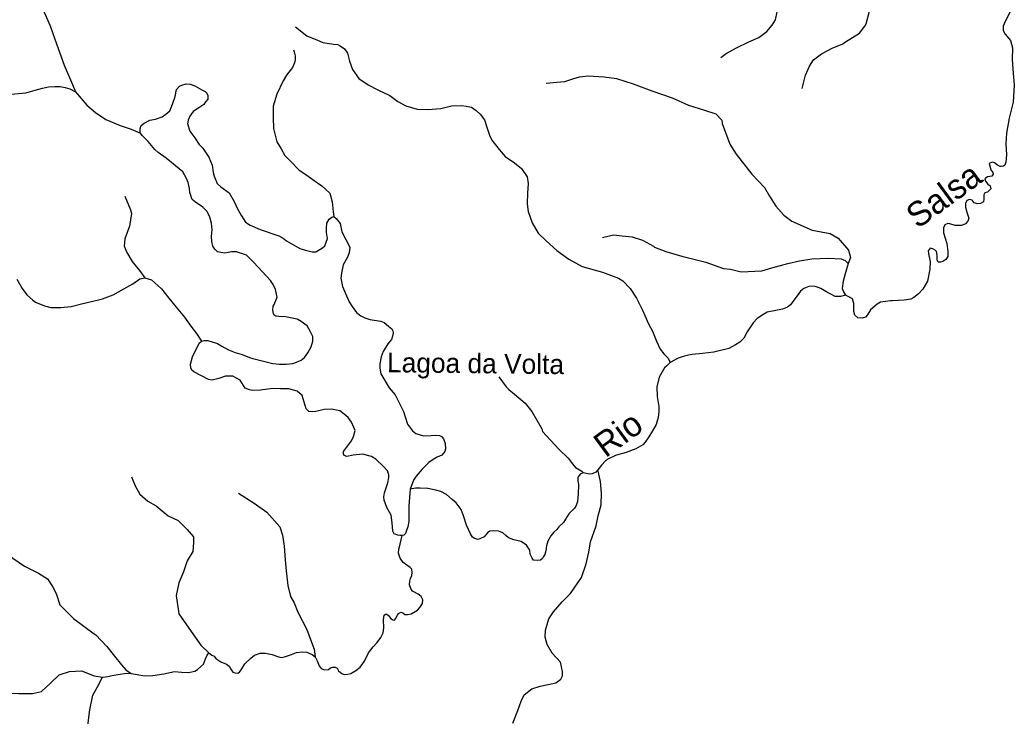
# Model space of a CAD drawing. Extents: x 436.3 to 500.4, y 8231 to 8286.4.
# Drawn here: x 484.1 to 492.19, y 8252.95 to 8258.62 of the extents above; entities that cross this region are included whole.
import ezdxf
from ezdxf.enums import TextEntityAlignment as Align

# ---------------------------------------------------------------- set-up
doc = ezdxf.new("R2010")
doc.units = 0
doc.header["$LTSCALE"] = 0.08
doc.linetypes.add('LONG_DASHED', pattern=[7.5, 6, -1.5])
doc.layers.add('2', color=7, linetype='Continuous', lineweight=25)
doc.layers.add('9', color=7, linetype='LONG_DASHED', lineweight=25)
doc.layers.add('61', color=7, linetype='Continuous')

msp = doc.modelspace()

# ---------------------------------------------------------------- linework, layer by layer
at = {"layer": '2'}
for points in [[(485.0847, 8257.6929), (485.0821, 8257.7061), (485.082, 8257.7324), (485.0899, 8257.7561), (485.1137, 8257.7746), (485.1602, 8257.8), (485.2053, 8257.809), (485.2594, 8257.8271), (485.2909, 8257.8495), (485.3225, 8257.8765), (485.3449, 8257.9304), (485.3673, 8257.9932), (485.3781, 8258.0488), (485.4019, 8258.0752), (485.4204, 8258.0858), (485.4549, 8258.0963), (485.4894, 8258.0937), (485.5265, 8258.0779), (485.5822, 8258.0464), (485.6114, 8258.0333), (485.6247, 8258.0201), (485.6328, 8258.0017), (485.6328, 8257.9701), (485.6142, 8257.9491), (485.5984, 8257.928), (485.5587, 8257.8989), (485.5138, 8257.87), (485.485, 8257.8319), (485.4715, 8257.8004), (485.4671, 8257.769), (485.4853, 8257.7107), (485.526, 8257.6569), (485.5622, 8257.6031), (485.5917, 8257.5731), (485.6391, 8257.5), (485.6663, 8257.4328), (485.6755, 8257.3744), (485.6846, 8257.343), (485.7072, 8257.2847), (485.7389, 8257.2578), (485.8066, 8257.2085), (485.8474, 8257.1368), (485.8746, 8257.0785), (485.9063, 8257.0201), (485.9379, 8256.9708), (485.9774, 8256.9466), (486.057, 8256.9098), (486.2088, 8256.8589), (486.245, 8256.841), (486.2721, 8256.8186), (486.3804, 8256.7558), (486.4256, 8256.7424), (486.4797, 8256.729), (486.5113, 8256.729), (486.5654, 8256.7605), (486.5834, 8256.7785), (486.6059, 8256.8369), (486.5968, 8256.8863), (486.5967, 8256.9222), (486.6011, 8256.9626), (486.6189, 8256.9948), (486.64, 8257.0107), (486.656, 8257.0159)], [(485.7714, 8256.719), (485.737, 8256.7218), (485.7104, 8256.7296), (485.6892, 8256.7507), (485.6732, 8256.7744), (485.6653, 8256.8113), (485.6629, 8256.8536), (485.6673, 8256.9075), (485.6627, 8256.9614), (485.6491, 8257.0108), (485.6265, 8257.0557), (485.5903, 8257.0915), (485.5316, 8257.1318), (485.5045, 8257.1542), (485.4863, 8257.2126), (485.4817, 8257.244), (485.4726, 8257.2934), (485.459, 8257.3248), (485.4273, 8257.3786), (485.2917, 8257.4906), (485.2285, 8257.5354), (485.2014, 8257.5623), (485.1471, 8257.625), (485.0974, 8257.6743), (485.0847, 8257.6929)], [(486.656, 8257.0159), (486.6772, 8257.0001), (486.7091, 8256.958), (486.7231, 8256.8909), (486.7864, 8256.7653), (486.782, 8256.7204), (486.7685, 8256.6844), (486.7325, 8256.6215), (486.7191, 8256.5541)], [(486.1643, 8256.4635), (486.1417, 8256.4949), (486.0061, 8256.643), (485.9464, 8256.7009), (485.8661, 8256.7282), (485.8255, 8256.7281), (485.7714, 8256.719)], [(486.7191, 8256.5541), (486.7146, 8256.5137), (486.7282, 8256.4463), (486.7599, 8256.3699), (486.7825, 8256.3205), (486.8051, 8256.2845), (486.8412, 8256.2351)], [(485.5801, 8256.0018), (485.6013, 8256.0071), (485.6332, 8256.0072), (485.71, 8255.9835), (485.7472, 8255.9599), (485.7991, 8255.9323), (485.8533, 8255.9099), (485.9119, 8255.892), (485.9706, 8255.8696), (485.9977, 8255.8606), (486.1601, 8255.8204), (486.2142, 8255.816), (486.2684, 8255.816), (486.3225, 8255.8206), (486.3541, 8255.8296), (486.3902, 8255.8477), (486.4173, 8255.8702), (486.4443, 8255.9063), (486.4714, 8255.9558), (486.4868, 8256.0031), (486.4868, 8256.0401), (486.4683, 8256.0771), (486.4398, 8256.1267), (486.3901, 8256.1626), (486.3585, 8256.1806), (486.3179, 8256.1895), (486.2637, 8256.1984), (486.2096, 8256.2028), (486.1845, 8256.206), (486.1712, 8256.2139), (486.166, 8256.227), (486.1606, 8256.2534), (486.1632, 8256.2878), (486.1711, 8256.301), (486.1959, 8256.3602), (486.1823, 8256.4231), (486.1643, 8256.4635)], [(486.8412, 8256.2351), (486.8773, 8256.2082), (486.9089, 8256.1903), (486.9495, 8256.1768), (487.0387, 8256.1647), (487.0653, 8256.1541), (487.1024, 8256.1225), (487.1303, 8256.1014), (487.1382, 8256.0856), (487.1408, 8256.0698), (487.1356, 8256.0434), (487.125, 8256.0143), (487.0958, 8255.98), (487.0588, 8255.9165), (487.0428, 8255.8742), (487.0308, 8255.817), (487.0308, 8255.781), (487.0398, 8255.736), (487.1074, 8255.6234), (487.1569, 8255.5649), (487.2244, 8255.4298), (487.2558, 8255.3262), (487.2963, 8255.2721), (487.3233, 8255.2496), (487.3864, 8255.2316), (487.4488, 8255.2334), (487.4806, 8255.236), (487.5176, 8255.2334), (487.5335, 8255.2255), (487.5493, 8255.207), (487.5625, 8255.1699), (487.5651, 8255.1223), (487.5598, 8255.1037), (487.5359, 8255.0746), (487.4988, 8255.0587), (487.4644, 8255.0402), (487.4311, 8255.0151), (487.3769, 8254.9609), (487.3272, 8254.9023), (487.3046, 8254.8707), (487.2775, 8254.7985)], [(487.2123, 8254.4221), (487.1938, 8254.4221), (487.1779, 8254.4247), (487.1489, 8254.4354), (487.1383, 8254.4565), (487.1327, 8254.5231), (487.1238, 8254.5863), (487.0879, 8254.6495), (487.0655, 8254.7081), (487.0628, 8254.7355), (487.0682, 8254.7673), (487.0975, 8254.8493), (487.1055, 8254.8917), (487.1055, 8254.9156), (487.0924, 8254.9473), (487.0633, 8254.979), (486.9985, 8255.0419), (486.9624, 8255.0645), (486.8903, 8255.0824), (486.8137, 8255.0734), (486.764, 8255.0636), (486.7402, 8255.0715), (486.7349, 8255.0847), (486.7349, 8255.1033), (486.8003, 8255.1906), (486.8184, 8255.2267), (486.832, 8255.2763), (486.8005, 8255.3438), (486.7734, 8255.3798), (486.7419, 8255.4069), (486.7058, 8255.4338), (486.6382, 8255.4473), (486.5795, 8255.4472), (486.5119, 8255.4291), (486.4809, 8255.4257), (486.4543, 8255.4309), (486.4332, 8255.452), (486.3992, 8255.5596), (486.3586, 8255.5956), (486.2909, 8255.6135), (486.2232, 8255.6134), (486.1601, 8255.6178), (486.0608, 8255.6042), (485.9976, 8255.5996), (485.9698, 8255.6048), (485.9354, 8255.6207), (485.8939, 8255.685), (485.8352, 8255.7164), (485.7766, 8255.7163), (485.7224, 8255.6982), (485.6683, 8255.6846), (485.6367, 8255.6891), (485.5194, 8255.7519), (485.5006, 8255.7667), (485.4926, 8255.7851), (485.49, 8255.8142), (485.5086, 8255.8749), (485.5616, 8255.986), (485.5801, 8256.0018)], [(487.2775, 8254.7985), (487.2682, 8254.6631), (487.2679, 8254.5366), (487.2601, 8254.491), (487.2494, 8254.4619), (487.2389, 8254.438), (487.2255, 8254.4248), (487.2123, 8254.4221)]]:
    msp.add_lwpolyline(points, dxfattribs=at)
at = {"layer": '9'}
for points in [[(481.9907, 8259.6476), (482.0749, 8259.5359), (482.1958, 8259.4436), (482.3057, 8259.4173), (482.4206, 8259.4226), (482.576, 8259.4332), (482.728, 8259.4578), (482.8587, 8259.4684), (482.9719, 8259.4473), (483.1771, 8259.405), (483.354, 8259.3628), (483.6512, 8259.3031), (483.7893, 8259.2609), (483.8886, 8259.2118), (484.0056, 8259.1308), (484.1034, 8259.0383), (484.1461, 8258.9784), (484.2137, 8258.8624), (484.2635, 8258.7639), (484.349, 8258.5669), (484.3882, 8258.4578), (484.4632, 8258.2467), (484.531, 8258.0902), (484.5562, 8258.0303)], [(489.8053, 8258.3089), (489.8484, 8258.3426), (489.9336, 8258.3874), (490.0338, 8258.4371), (490.114, 8258.4719), (490.1791, 8258.5217), (490.2241, 8258.5716), (490.2492, 8258.6165), (490.2641, 8258.6815), (490.3192, 8258.7514), (490.3592, 8258.7813), (490.4344, 8258.8261), (490.5145, 8258.8409), (490.6048, 8258.8407), (490.6901, 8258.8355), (490.8857, 8258.8051), (490.9758, 8258.8084), (491.0602, 8258.822)], [(490.4661, 8258.0568), (490.4932, 8258.1656), (490.5281, 8258.2394), (490.5592, 8258.2899), (490.6253, 8258.3402), (490.711, 8258.3867), (490.7968, 8258.4215), (490.8201, 8258.437), (490.9331, 8258.5067), (490.9759, 8258.5649), (490.9876, 8258.5844), (491.0114, 8258.6752), (491.0238, 8258.743), (491.0602, 8258.822)], [(492.1629, 8258.686), (492.1194, 8258.6031), (492.1036, 8258.5637), (492.1037, 8258.5282), (492.1196, 8258.5006), (492.1633, 8258.447), (492.1792, 8258.3878), (492.1755, 8258.2931), (492.1836, 8258.1827), (492.1916, 8258.0841), (492.184, 8257.946), (492.1525, 8257.8158), (492.1289, 8257.6934), (492.1249, 8257.6079), (492.1283, 8257.517), (492.1245, 8257.4578), (492.1166, 8257.4341), (492.1047, 8257.4263), (492.0849, 8257.4223), (492.077, 8257.4223), (492.0571, 8257.4341), (492.0333, 8257.4538), (492.0135, 8257.4578), (491.9897, 8257.446), (492.0017, 8257.3947), (492.0175, 8257.3749), (492.0215, 8257.3591), (492.0097, 8257.3433), (491.974, 8257.3394), (491.9542, 8257.3235), (491.9582, 8257.3038), (491.9781, 8257.2801), (491.9979, 8257.2644), (492.0019, 8257.2406), (491.9742, 8257.213), (491.9544, 8257.209), (491.9464, 8257.1932), (491.9464, 8257.1577), (491.9426, 8257.134), (491.9188, 8257.1222), (491.891, 8257.1182), (491.8673, 8257.1262), (491.8514, 8257.1499), (491.8276, 8257.1538), (491.8078, 8257.1459), (491.7959, 8257.1222), (491.796, 8257.0906), (491.8079, 8257.0511), (491.8225, 8257.0028), (491.8146, 8256.979), (491.7948, 8256.9553), (491.7631, 8256.9435), (491.7116, 8256.9435), (491.668, 8256.9554), (491.6521, 8256.9594), (491.6284, 8256.9475), (491.6165, 8256.9238), (491.6165, 8256.8843), (491.6444, 8256.7973), (491.6523, 8256.7301), (491.6524, 8256.6906), (491.6366, 8256.6669), (491.6129, 8256.6511), (491.593, 8256.6432), (491.5732, 8256.6432), (491.5652, 8256.663), (491.5652, 8256.7026), (491.5613, 8256.7302), (491.5494, 8256.7421), (491.5295, 8256.7539), (491.5094, 8256.7576), (491.4936, 8256.7378), (491.4976, 8256.6982), (491.5095, 8256.6508), (491.5056, 8256.5876), (491.4859, 8256.4887), (491.4503, 8256.4255), (491.4146, 8256.386), (491.375, 8256.3583), (491.3513, 8256.3425)], [(486.3461, 8258.5589), (486.4368, 8258.4864), (486.5244, 8258.4517), (486.5683, 8258.4315), (486.6534, 8258.4193), (486.6884, 8258.4164), (486.7088, 8258.4048), (486.7439, 8258.3788), (486.7674, 8258.344), (486.785, 8258.2802), (486.8085, 8258.2107), (486.8612, 8258.1383), (486.9372, 8258.0861), (487.016, 8258.0456), (487.1125, 8257.9992), (487.1767, 8257.9528), (487.2439, 8257.9151), (487.3343, 8257.8891), (487.4218, 8257.8862), (487.5278, 8257.8941), (487.6152, 8257.9173), (487.6938, 8257.9201), (487.7347, 8257.9143), (487.7784, 8257.9056), (487.8164, 8257.8795), (487.8485, 8257.8476), (487.8836, 8257.8012), (487.9012, 8257.7433), (487.9246, 8257.6766), (487.9422, 8257.6359), (488.0012, 8257.5622), (488.051, 8257.5042), (488.1268, 8257.4519), (488.1851, 8257.4055), (488.2289, 8257.3388), (488.2377, 8257.2837), (488.2321, 8257.2053), (488.2295, 8257.1184), (488.2383, 8257.0575), (488.2706, 8256.9647), (488.3203, 8256.8792), (488.3844, 8256.8182), (488.4718, 8256.7398), (488.5679, 8256.67), (488.6785, 8256.6088), (488.8442, 8256.562), (488.9721, 8256.5153), (489.007, 8256.4919), (489.0688, 8256.4292), (489.1182, 8256.3506), (489.1677, 8256.2546), (489.2171, 8256.1441), (489.2491, 8256.083), (489.2811, 8256.0015), (489.3131, 8255.9374), (489.3421, 8255.8996), (489.3769, 8255.8646), (489.3925, 8255.8288)], [(486.3287, 8258.3725), (486.3345, 8258.3551), (486.3434, 8258.3232), (486.3435, 8258.2913), (486.3376, 8258.2653), (486.3203, 8258.2275), (486.2707, 8258.1667), (486.2445, 8258.1202), (486.1923, 8258.01), (486.1633, 8257.9142), (486.1635, 8257.8215), (486.1666, 8257.7316), (486.1932, 8257.6243), (486.2284, 8257.5663), (486.2578, 8257.5125), (486.3075, 8257.4632), (486.3748, 8257.3937), (486.4362, 8257.3531), (486.4976, 8257.3097), (486.559, 8257.2662), (486.6233, 8257.2054), (486.6439, 8257.1358), (486.6529, 8257.0545), (486.656, 8257.0159)], [(488.3834, 8258.1009), (488.4703, 8258.1094), (488.5355, 8258.1136), (488.6006, 8258.1352), (488.6571, 8258.1523), (488.7266, 8258.1609), (488.8569, 8258.152), (488.9569, 8258.1388), (489.0915, 8258.0953), (489.2436, 8258.0386), (489.4087, 8257.982), (489.5434, 8257.921), (489.6737, 8257.8817), (489.7648, 8257.8512), (489.8127, 8257.7992), (489.8171, 8257.7732), (489.8781, 8257.6042), (489.9303, 8257.5218), (490.0565, 8257.3613), (490.1619, 8257.2513), (490.201, 8257.1818), (490.2533, 8257.0995), (490.3184, 8257.0256), (490.3836, 8256.9778), (490.5486, 8256.9038), (490.6961, 8256.8775), (490.7612, 8256.8384), (490.8438, 8256.7429), (490.8612, 8256.6822), (490.8414, 8256.6344)], [(483.3616, 8258.0878), (483.37, 8258.0627), (483.3954, 8257.9985), (483.4151, 8257.9679), (483.446, 8257.94), (483.4937, 8257.9261), (483.5469, 8257.9149), (483.5975, 8257.9178), (483.6535, 8257.9346), (483.7094, 8257.9597), (483.8075, 8257.9849), (483.914, 8258.0017), (484.0625, 8258.013), (484.1523, 8258.0215), (484.228, 8258.0439), (484.2869, 8258.0607), (484.3345, 8258.0719), (484.3878, 8258.0748), (484.4299, 8258.0748), (484.472, 8258.0665), (484.5085, 8258.0554), (484.5562, 8258.0303)], [(484.5562, 8258.0303), (484.6483, 8257.9213), (484.7194, 8257.8615), (484.801, 8257.8053), (484.9181, 8257.7561), (485.0076, 8257.7269), (485.0847, 8257.6929)], [(484.9573, 8257.1819), (485.0022, 8257.0709), (485.0097, 8257.0413), (484.9949, 8256.9376), (484.9579, 8256.8339), (484.9506, 8256.7746), (484.973, 8256.7228), (485.0177, 8256.6488), (485.0849, 8256.5668), (485.1182, 8256.5163)], [(488.8417, 8256.8456), (488.9328, 8256.8671), (489.0023, 8256.8583), (489.0848, 8256.8494), (489.1672, 8256.8232), (489.2585, 8256.7753), (489.2671, 8256.7666), (489.3582, 8256.7317), (489.4885, 8256.6924), (489.6837, 8256.6442), (489.827, 8256.5919), (489.8833, 8256.5874), (489.9702, 8256.5655), (490.1393, 8256.5738), (490.2217, 8256.5997), (490.3496, 8256.6337), (490.445, 8256.6553), (490.5448, 8256.6723), (490.6837, 8256.6765), (490.7835, 8256.6719), (490.8182, 8256.6576), (490.8414, 8256.6344)], [(490.8414, 8256.6344), (490.8183, 8256.5508), (490.801, 8256.4901), (490.7924, 8256.4294), (490.8042, 8256.4032), (490.8192, 8256.3747)], [(484.0784, 8256.5057), (484.1212, 8256.4305), (484.1606, 8256.3782), (484.2067, 8256.339), (484.2297, 8256.3193), (484.302, 8256.29), (484.3546, 8256.2769), (484.4368, 8256.277), (484.519, 8256.2837), (484.6044, 8256.3067), (484.6867, 8256.3232), (484.7764, 8256.3456), (484.8619, 8256.3784), (484.9473, 8256.4276), (485.0229, 8256.4671), (485.0787, 8256.5097), (485.1182, 8256.5163)], [(485.1182, 8256.5163), (485.1743, 8256.5003), (485.2563, 8256.4263), (485.316, 8256.3522), (485.3756, 8256.2782), (485.4427, 8256.1968), (485.4948, 8256.1227), (485.5396, 8256.0635), (485.5801, 8256.0018)], [(490.8192, 8256.3747), (490.7799, 8256.3662), (490.7351, 8256.3663), (490.6956, 8256.386), (490.6592, 8256.4058), (490.6199, 8256.4311), (490.5974, 8256.4395), (490.5638, 8256.4481), (490.5216, 8256.4454), (490.4795, 8256.4314), (490.4543, 8256.409), (490.4262, 8256.3697), (490.3982, 8256.3361), (490.373, 8256.2968), (490.3477, 8256.2773), (490.3084, 8256.2633), (490.2382, 8256.2493), (490.1838, 8256.2372), (490.1473, 8256.2148), (490.1024, 8256.1868), (490.0687, 8256.1503), (490.0211, 8256.0774), (489.993, 8256.0269), (489.9593, 8255.9933), (489.9257, 8255.9709), (489.8696, 8255.943), (489.7488, 8255.9122), (489.6562, 8255.9013), (489.5721, 8255.8931), (489.53, 8255.8847), (489.4907, 8255.8736), (489.4598, 8255.8623), (489.3925, 8255.8288)], [(491.0227, 8256.2558), (490.999, 8256.2162), (490.9831, 8256.1965), (490.9554, 8256.1886), (490.9198, 8256.1927), (490.896, 8256.2125), (490.8881, 8256.2442), (490.8881, 8256.3075), (490.8762, 8256.347), (490.8525, 8256.3589), (490.8192, 8256.3747)], [(491.3513, 8256.3425), (491.2958, 8256.3346), (491.2008, 8256.3308), (491.185, 8256.3308), (491.1058, 8256.319), (491.0781, 8256.3032), (491.0227, 8256.2558)], [(489.3925, 8255.8288), (489.3672, 8255.8007), (489.3471, 8255.7859), (489.305, 8255.7101), (489.2853, 8255.6313), (489.2881, 8255.5525), (489.3021, 8255.471), (489.302, 8255.4287), (489.2963, 8255.3809), (489.2794, 8255.3246), (489.2485, 8255.2711), (489.2203, 8255.2233), (489.1895, 8255.1812), (489.1716, 8255.1575), (489.1154, 8255.1267), (489.0367, 8255.0958), (488.9581, 8255.0734), (488.9496, 8255.0706), (488.8906, 8255.0454), (488.8681, 8255.0285), (488.8343, 8254.992), (488.8062, 8254.9553)], [(488.0002, 8255.7118), (488.0594, 8255.6301), (488.0817, 8255.6077), (488.1261, 8255.5705), (488.215, 8255.4961), (488.2669, 8255.4293), (488.3483, 8255.2879), (488.3556, 8255.2657), (488.4889, 8255.1242), (488.5629, 8255.0497), (488.5999, 8255.0051), (488.6221, 8254.9752), (488.6738, 8254.9437), (488.6882, 8254.9301)], [(488.1144, 8252.8935), (488.1549, 8252.9971), (488.1819, 8253.0736), (488.2043, 8253.1232), (488.2672, 8253.1727), (488.3345, 8253.1952), (488.4511, 8253.2189), (488.4645, 8253.2234), (488.5049, 8253.2508), (488.5183, 8253.2778), (488.5184, 8253.3139), (488.5006, 8253.3904), (488.4335, 8253.4625), (488.3934, 8253.5346), (488.3756, 8253.5931), (488.3802, 8253.6515), (488.4072, 8253.7415), (488.4432, 8253.8), (488.515, 8253.881), (488.5824, 8253.9483), (488.6722, 8254.0787), (488.7092, 8254.19), (488.7318, 8254.2844), (488.7454, 8254.3698), (488.7904, 8254.5001), (488.8086, 8254.5809), (488.8311, 8254.6708), (488.8358, 8254.7651), (488.827, 8254.8594), (488.8062, 8254.9553)], [(488.8062, 8254.9553), (488.7893, 8254.9356), (488.7583, 8254.9216), (488.7331, 8254.9188), (488.6882, 8254.9301)], [(485.0108, 8254.8993), (485.0405, 8254.825), (485.0776, 8254.7581), (485.1445, 8254.6988), (485.2115, 8254.6617), (485.3081, 8254.5799), (485.39, 8254.5428), (485.4643, 8254.4685), (485.5163, 8254.4091), (485.5163, 8254.3645), (485.5087, 8254.2901), (485.4639, 8254.2156), (485.434, 8254.1262), (485.3966, 8254.0369), (485.3742, 8253.9326), (485.3961, 8253.7837), (485.5153, 8253.6115), (485.5747, 8253.5296), (485.641, 8253.466)], [(488.6882, 8254.9301), (488.663, 8254.9232), (488.6417, 8254.8964), (488.6416, 8254.8642), (488.6463, 8254.8369), (488.6461, 8254.7566), (488.6406, 8254.6976), (488.6299, 8254.6656), (488.6138, 8254.6441), (488.5681, 8254.5963), (488.5424, 8254.5543), (488.5261, 8254.5263), (488.4889, 8254.4914), (488.4703, 8254.4704), (488.4469, 8254.4471), (488.4213, 8254.4192), (488.3979, 8254.3748), (488.3885, 8254.3375), (488.3815, 8254.2955), (488.3745, 8254.2652), (488.3628, 8254.2489), (488.3535, 8254.2349), (488.3395, 8254.2209), (488.314, 8254.2186), (488.2814, 8254.2209), (488.2698, 8254.2373), (488.2536, 8254.2676), (488.2513, 8254.3004), (488.2258, 8254.3423), (488.1817, 8254.3727), (488.1213, 8254.3868), (488.0794, 8254.4031), (488.0563, 8254.4195), (488.0307, 8254.4428), (488.0005, 8254.4568), (487.9563, 8254.4592), (487.9261, 8254.4569), (487.9075, 8254.4428), (487.8794, 8254.4102), (487.8515, 8254.3963), (487.8306, 8254.3893), (487.8026, 8254.3963), (487.7864, 8254.408), (487.7701, 8254.4336), (487.7354, 8254.5059), (487.7123, 8254.5806), (487.6928, 8254.632), (487.6533, 8254.6857), (487.6207, 8254.7137), (487.5743, 8254.7533), (487.5278, 8254.779), (487.4859, 8254.7883), (487.423, 8254.8022), (487.3601, 8254.8069), (487.3205, 8254.8069), (487.2775, 8254.7985)], [(485.882, 8254.7654), (486.0084, 8254.6838), (486.1125, 8254.6095), (486.2165, 8254.4906), (486.2388, 8254.4236), (486.2536, 8254.3343), (486.2608, 8254.2227), (486.268, 8254.1333), (486.2827, 8254.0142), (486.3049, 8253.9248), (486.3346, 8253.8726), (486.3642, 8253.7982), (486.4384, 8253.6567), (486.4754, 8253.5524), (486.4976, 8253.4951), (486.5044, 8253.4328)], [(486.5044, 8253.4328), (486.5209, 8253.402), (486.5374, 8253.3618), (486.5539, 8253.3381), (486.5823, 8253.3286), (486.613, 8253.331), (486.6296, 8253.3452), (486.6485, 8253.3499), (486.6673, 8253.35), (486.6839, 8253.3405), (486.6957, 8253.3191), (486.7216, 8253.2978), (486.7406, 8253.2908), (486.7713, 8253.2931), (486.7949, 8253.2978), (486.8374, 8253.3215), (486.8706, 8253.35), (486.9062, 8253.3997), (486.9393, 8253.466), (486.9775, 8253.5141), (487.0083, 8253.5497), (487.039, 8253.5923), (487.058, 8253.6278), (487.0652, 8253.6705), (487.0606, 8253.7344), (487.0677, 8253.7722), (487.0772, 8253.7817), (487.089, 8253.7817), (487.1008, 8253.7699), (487.1173, 8253.7485), (487.1362, 8253.7344), (487.1503, 8253.7319), (487.1598, 8253.7415), (487.174, 8253.7722), (487.1836, 8253.7864), (487.2024, 8253.7982), (487.219, 8253.7912), (487.2355, 8253.7794), (487.2567, 8253.7794), (487.2875, 8253.7841), (487.3371, 8253.8125), (487.356, 8253.8338), (487.3797, 8253.8669), (487.3822, 8253.8977), (487.368, 8253.9237), (487.3421, 8253.9427), (487.2972, 8253.9687), (487.2832, 8253.99), (487.2737, 8254.0184), (487.2765, 8254.0505), (487.2812, 8254.0719), (487.2908, 8254.0955), (487.2932, 8254.1192), (487.2909, 8254.1476), (487.2791, 8254.1618), (487.2508, 8254.1807), (487.2202, 8254.202), (487.1966, 8254.2351), (487.1825, 8254.2777), (487.1849, 8254.3084), (487.1969, 8254.3511), (487.2123, 8254.4221)], [(483.8935, 8254.3215), (484.0025, 8254.2654), (484.1398, 8254.1725), (484.255, 8254.1149), (484.3275, 8254.0687), (484.3674, 8254.0066), (484.3983, 8253.949), (484.4292, 8253.8559), (484.4513, 8253.8336), (484.5398, 8253.745), (484.7082, 8253.6208), (484.7215, 8253.6119), (484.8101, 8253.5188), (484.872, 8253.4389), (484.9296, 8253.3679), (484.965, 8253.3279), (485.0083, 8253.2985)], [(485.0083, 8253.2985), (485.1185, 8253.2781), (485.1847, 8253.2805), (485.2747, 8253.2948), (485.3598, 8253.3137), (485.4189, 8253.309), (485.4756, 8253.3066), (485.5253, 8253.3162), (485.549, 8253.3304), (485.5964, 8253.373), (485.613, 8253.418), (485.6271, 8253.4464), (485.641, 8253.466)], [(485.641, 8253.466), (485.6658, 8253.4462), (485.6823, 8253.4391), (485.6981, 8253.4204), (485.7382, 8253.3943), (485.7832, 8253.373), (485.8044, 8253.3565), (485.8186, 8253.3329), (485.8364, 8253.3094), (485.8529, 8253.3024), (485.8765, 8253.3), (485.8908, 8253.3094), (485.9098, 8253.3354), (485.9335, 8253.3757), (485.9808, 8253.4231), (486.0116, 8253.4467), (486.0566, 8253.4633), (486.1015, 8253.4634), (486.1559, 8253.4539), (486.1983, 8253.4374), (486.2291, 8253.4279), (486.2551, 8253.4327), (486.3119, 8253.454), (486.3545, 8253.4681), (486.3994, 8253.4753), (486.4372, 8253.4706), (486.4797, 8253.4516), (486.5044, 8253.4328)], [(483.5447, 8253.2522), (483.6213, 8253.2409), (483.7755, 8253.2092), (483.8436, 8253.1672), (483.9485, 8253.141), (484.0954, 8253.1358), (484.2057, 8253.1359), (484.2792, 8253.1518), (484.3529, 8253.2202), (484.4213, 8253.2886), (484.5053, 8253.315), (484.6051, 8253.3203), (484.7077, 8253.2792), (484.7742, 8253.268)], [(485.3486, 8251.8449), (485.2837, 8251.874), (485.2389, 8251.9194), (485.1947, 8251.9847), (485.0964, 8252.1237), (485.022, 8252.1908), (484.8658, 8252.2877), (484.7839, 8252.3622), (484.7097, 8252.4816), (484.6652, 8252.6082), (484.6504, 8252.7051), (484.6506, 8252.8318), (484.6732, 8253.0032), (484.6957, 8253.1225), (484.7331, 8253.1895), (484.7742, 8253.268)], [(484.7742, 8253.268), (484.8187, 8253.2734), (484.8397, 8253.2789), (484.9003, 8253.2893), (484.9739, 8253.2998), (485.0083, 8253.2985)]]:
    msp.add_lwpolyline(points, dxfattribs=at)

# ---------------------------------------------------------------- texts
at = {"layer": '61'}
msp.add_text('Rio                                     Salsa', height=0.2, rotation=36.247, dxfattribs=at).set_placement((490.4071, 8256.1769), align=Align.CENTER)
msp.add_text('Lagoa da Volta', height=0.16, rotation=359.377, dxfattribs=at).set_placement((487.0895, 8255.7491))

doc.saveas('drawing.dxf')
